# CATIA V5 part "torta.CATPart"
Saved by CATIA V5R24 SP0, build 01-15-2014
Part number: torta
Bounding box of the stored display mesh (mm): x 0 to 230, y -110 to 110, z -141 to 141
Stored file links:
  C:\Users\Fatec\Desktop\Maquina componentes catia\torta.CATPart
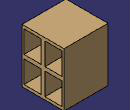
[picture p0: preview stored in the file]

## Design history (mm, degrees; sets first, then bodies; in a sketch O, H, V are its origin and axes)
Body1 (main body)
  Sketch1 on yz-plane, origin (0, 0, 0), H (0, 1, 0), V (0, 0, 1)
    line L1 (-110, 141) -> (110, 141)
    line L2 (110, 141) -> (110, -141)
    line L3 (110, -141) -> (-110, -141)
    line L4 (-110, -141) -> (-110, 141)
    length L3 = 220
    length L2 = 282
    horizontal: L1 H, L3 H
    vertical: L2 V, L4 V
    symmetry: L4 L2 V, L3 L1 H
  Pad1: profile Sketch1, direction (1, 0, 0), length 230
  Sketch2 on end face of Pad1, origin (230, 0, 0), H (0, 1, 0), V (0, 0, 1)
    point P1 (-110, -141)
    reference projected line E2 (-110, 141) -> (-110, -141) from edge [face of Pad1 from Sketch1.L4 | end face of Pad1]
    point P3 (-110, 141)
    point P4 (-110, -141)
    reference projected line E3 (110, 141) -> (-110, 141) from edge [face of Pad1 from Sketch1.L1 | end face of Pad1]
    point P6 (-110, 141)
    point P9 (-100, 126)
    line L1 (-100, 126) -> (-10, 126)
    line L2 (-10, 126) -> (-10, 10)
    line L3 (-10, 10) -> (-100, 10)
    line L4 (-100, 10) -> (-100, 126)
    point P10 (-10, 126)
    point P11 (-10, 10)
    point P12 (-100, 10)
    point P13 (-110, -141)
    point P14 (-110, -141)
    point P15 (-100, -126)
    point P16 (-10, -126)
    point P17 (-10, -10)
    point P18 (-100, -10)
    line L5 (-100, -126) -> (-10, -126)
    line L6 (-10, -126) -> (-10, -10)
    line L7 (-10, -10) -> (-100, -10)
    line L8 (-100, -10) -> (-100, -126)
    point P19 (110, -141)
    point P20 (110, -141)
    point P21 (110, 141)
    point P22 (110, 141)
    point P23 (100, 126)
    point P24 (10, 126)
    point P25 (10, 10)
    point P26 (100, 10)
    point P27 (110, -141)
    point P28 (110, -141)
    point P29 (100, -126)
    point P30 (10, -126)
    point P31 (10, -10)
    point P32 (100, -10)
    line L9 (100, 126) -> (10, 126)
    line L10 (10, 126) -> (10, 10)
    line L11 (10, 10) -> (100, 10)
    line L12 (100, 10) -> (100, 126)
    line L13 (100, -126) -> (10, -126)
    line L14 (10, -126) -> (10, -10)
    line L15 (10, -10) -> (100, -10)
    line L16 (100, -10) -> (100, -126)
    construction line L17 (110, 141) -> (110, -141)
    distance L4 E2 = 10
    distance L1 E3 = 15
    distance L2 V = 10
    distance L3 H = 10
    horizontal: L1 H, L3 H
    vertical: L2 V, L4 V
    symmetry: P3 P13 H, P6 P14 H, P9 P15 H, P10 P16 H, P11 P17 H, P12 P18 H, L1 L5 H, L2 L6 H, L3 L7 H, L4 L8 H, P1 P19 V, P4 P20 V, P3 P21 V, E2 L17 V, P6 P22 V, P9 P23 V, P10 P24 V, P11 P25 V, P12 P26 V, P13 P27 V, P14 P28 V, P15 P29 V, P16 P30 V, P17 P31 V, P18 P32 V, L1 L9 V, L2 L10 V, L3 L11 V, L4 L12 V, L5 L13 V, L6 L14 V, L7 L15 V, L8 L16 V
  Pocket1: profile Sketch2, direction (-1, 0, 0), length 228
  Sketch3 on end face of Pocket1, origin (2, 0, 0), H (0, 1, 0), V (0, 0, 1)
    reference projected line E1 (10, 126) -> (10, 10) from edge [end face of Pad1 | face of Pocket1 from Sketch2.L10]
    reference projected line E2 (10, 10) -> (100, 10) from edge [end face of Pad1 | face of Pocket1 from Sketch2.L11]
    point P9 (53.5, 71.5)
    line L1 (53.5, 71.5) -> (56.5, 71.5)
    line L2 (56.5, 71.5) -> (56.5, 66.5)
    line L3 (56.5, 66.5) -> (53.5, 66.5)
    line L4 (53.5, 66.5) -> (53.5, 71.5)
    point P10 (56.5, 71.5)
    point P11 (56.5, 66.5)
    point P12 (53.5, 66.5)
    point P13 (-53.5, 71.5)
    point P14 (-56.5, 71.5)
    point P15 (-56.5, 66.5)
    point P16 (-53.5, 66.5)
    line L5 (-53.5, 71.5) -> (-56.5, 71.5)
    line L6 (-56.5, 71.5) -> (-56.5, 66.5)
    line L7 (-56.5, 66.5) -> (-53.5, 66.5)
    line L8 (-53.5, 66.5) -> (-53.5, 71.5)
    point P17 (53.5, -71.5)
    point P18 (56.5, -71.5)
    point P19 (56.5, -66.5)
    point P20 (53.5, -66.5)
    point P21 (-53.5, -71.5)
    point P22 (-56.5, -71.5)
    point P23 (-56.5, -66.5)
    point P24 (-53.5, -66.5)
    line L9 (53.5, -71.5) -> (56.5, -71.5)
    line L10 (56.5, -71.5) -> (56.5, -66.5)
    line L11 (56.5, -66.5) -> (53.5, -66.5)
    line L12 (53.5, -66.5) -> (53.5, -71.5)
    line L13 (-53.5, -71.5) -> (-56.5, -71.5)
    line L14 (-56.5, -71.5) -> (-56.5, -66.5)
    line L15 (-56.5, -66.5) -> (-53.5, -66.5)
    line L16 (-53.5, -66.5) -> (-53.5, -71.5)
    length L3 = 3
    length L2 = 5
    distance L4 E1 = 43.5
    distance L3 E2 = 56.5
    horizontal: L1 H, L3 H
    vertical: L2 V, L4 V
    symmetry: P9 P13 V, P10 P14 V, P11 P15 V, P12 P16 V, L1 L5 V, L2 L6 V, L3 L7 V, L4 L8 V, P9 P17 H, P10 P18 H, P11 P19 H, P12 P20 H, P13 P21 H, P14 P22 H, P15 P23 H, P16 P24 H, L1 L9 H, L2 L10 H, L3 L11 H, L4 L12 H, L5 L13 H, L6 L14 H, L7 L15 H, L8 L16 H
  Pocket2: profile Sketch3, direction (-1, 0, 0), through (limit type 6)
